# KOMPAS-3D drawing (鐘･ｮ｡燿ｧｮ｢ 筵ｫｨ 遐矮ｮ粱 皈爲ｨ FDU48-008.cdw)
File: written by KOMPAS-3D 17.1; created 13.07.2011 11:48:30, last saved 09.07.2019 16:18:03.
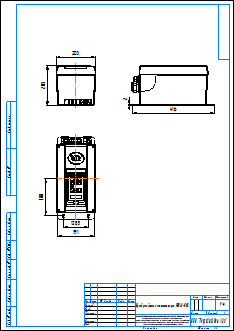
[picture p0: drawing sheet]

Title block, sheet 1: name: Преобразователи частоты серии FDU48-008; scale: 1:4; sheets: 1; sheet format: A3; stored path: \\adlc.lan\data\АДЛ_ПКД\3D-модели\Поставщики\Оборудование Emotron\Преобразователи частоты\Серия FDU 2.0\KOMPAS 2D\Преобразователи частоты серии FDU48-008.cdw

Views: Спереди 1
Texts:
  Рама для чертежей
  Лит-Масса-Масштаб
  Материал-Предприятие
  Масштаб
  Изм.
  Лист
  № докум.
  Подп.
  Дата
  Лит.
  Разраб.
  Пров.
  Т.контр.
  Листов
  Внимание! Данный продукт является объектом авторского права ООО «Торговый Дом АДЛ».
  Запрещается изменение, копирование, распространение
  (в том числе путем копирования на другие сайты и ресурсы в Интернете)
  или любое иное использование информации и объектов без предварительного
  согласия правообладателя (ООО «Торговый Дом АДЛ»).
  Н.контр.
  Утв.
  ООО "Торговый дом АДЛ"
  Изменение
  Номер документа
  Подпись
  Обозначение документа
  Наименование изделия
  Масса изделия по ГОСТ 2.109-73
  Порядковый номер листа
  Общее количество листов в документе
  Характер работы, выполненной лицом, подписавшим документ
  Наименование или индекс предприятия, выпускающего документ
  Инв. № подл.
  Подп. и дата
  Взам. инв. №
  Инв. № дубл.
  Инвентарный номер подлинника по ГОСТ 2.501-68
  Подпись принявшего подлинник в отдел технической документации
  Инвентарный номер подлинника, взамен которого выпущен данный подлинник
  Инвентарный номер дубликата по ГОСТ 2.502-68
  Подпись принявшего дубликат в отдел технической документации
  Справ. №
  Перв. примен.
  Обозначение документа, взамен или на основании которого выпущен данный документ
  Обозначение документа, в котором впервые записан данный документ
  Подпись лица, копировавшего чертеж
  Обозначение формата листа
  !Рама для чертежа
Dimensions and other numbers on the sheet: 203; 128,5; 191; 416; 2; 188; 1:4; 1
